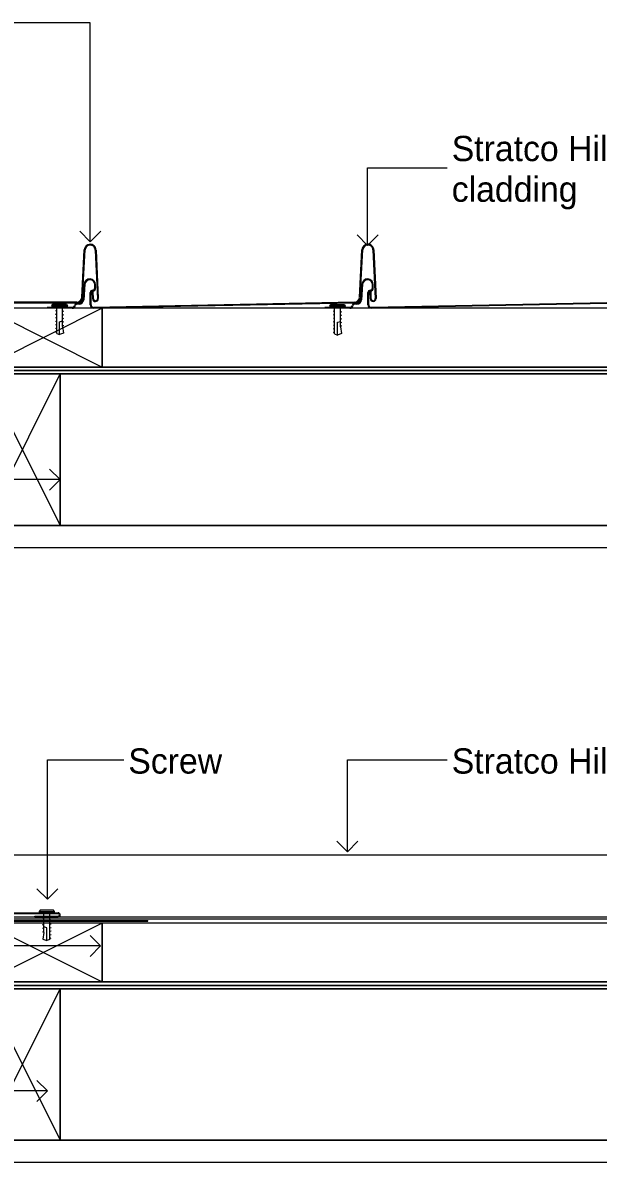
# Model space of a CAD drawing. Extents: x -2.36 to 6.66, y -3.72 to 4.13.
# Drawn here: x 4.016 to 4.358, y -3.642 to -2.966 of the extents above; entities that cross this region are included whole.
import ezdxf

# ---------------------------------------------------------------- set-up
doc = ezdxf.new("R2010")
doc.units = 0
for name, color, linetype in [('A-____-____-IDEN', 7, 'Continuous'), ('A-DETL-____-MEDM', 7, 'Continuous'), ('A-DETL-GENF-OTLN', 7, 'Continuous'), ('A-WALL-____-MCUT', 7, 'Continuous'), ('A-WALL-____-PATT', 7, 'Continuous'), ('A-WALL-FNSH-MCUT', 7, 'Continuous')]:
    doc.layers.add(name, color=color, linetype=linetype)

# ---------------------------------------------------------------- blocks, each defined once
blk = doc.blocks.new('Detail Repeating_Stratco_Hiland_Tray_Nailstrip - Rib Height 38mm_165mm Coverage-Detail Flashings - Hiland Nailstrip End Caps')
at = {"layer": 'A-DETL-____-MEDM'}
for p, q in [((0.50571, 0), (0.52057, 0)), ((0.52057, 0), (0.52057, -0.0005)), ((0.68557, 0), (0.68557, -0.0005)), ((0.338, -0.00303), (0.49297, 0)), ((0.338, -0.00353), (0.49298, -0.0005)), ((0.49148, -0.03459), (0.49017, -0.0057)), ((0.49198, -0.03457), (0.49067, -0.00568)), ((0.49301, -0.00561), (0.49313, -0.00979)), ((0.49351, -0.0056), (0.49363, -0.00977)), ((0.4945, -0.002), (0.4945, -0.00924)), ((0.495, -0.002), (0.495, -0.00924)), ((0.4995, -0.00635), (0.49802, -0.03464)), ((0.49814, -0.01418), (0.4988, -0.00504)), ((0.5, -0.00637), (0.49851, -0.03466)), ((0.49863, -0.01422), (0.49929, -0.00508)), ((0.50162, -0.00241), (0.50257, -0.00241)), ((0.50162, -0.00291), (0.50257, -0.00291)), ((0.503, -0.00303), (0.65797, 0)), ((0.503, -0.00353), (0.65798, -0.0005)), ((0.50571, -0.0005), (0.52057, -0.0005)), ((0.6595, -0.002), (0.6595, -0.00924)), ((0.66, -0.002), (0.66, -0.00924)), ((0.66314, -0.01418), (0.6638, -0.00504)), ((0.66363, -0.01422), (0.66429, -0.00508)), ((0.66662, -0.00241), (0.66757, -0.00241)), ((0.66662, -0.00291), (0.66757, -0.00291)), ((0.67071, -0.0005), (0.68557, -0.0005)), ((0.49179, -0.01206), (0.49179, -0.01397)), ((0.49229, -0.01206), (0.49229, -0.01397)), ((0.49363, -0.00977), (0.49313, -0.00979)), ((0.65679, -0.01206), (0.65679, -0.01397)), ((0.65729, -0.01206), (0.65729, -0.01397))]:
    blk.add_line(p, q, dxfattribs=at)
for centre, radius, start, end in [((0.493, -0.002), 0.002, 360, 90), ((0.50571, -0.0019), 0.0019, 90, 165.08957), ((0.658, -0.002), 0.002, 360, 90), ((0.67071, -0.0019), 0.0019, 90, 165.08957), ((0.49184, -0.00565), 0.00167, 91.69561, 181.73842), ((0.49184, -0.00565), 0.00117, 91.68553, 181.57145), ((0.49184, -0.00565), 0.00167, 1.72718, 91.74264), ((0.49184, -0.00565), 0.00117, 1.72718, 91.75272), ((0.493, -0.002), 0.0015, 0, 90), ((0.50162, -0.00525), 0.00283, 90, 175.86847), ((0.50162, -0.00525), 0.00233, 90, 175.86847), ((0.50299, -0.00653), 0.0035, 89.8838, 176.99932), ((0.50299, -0.00653), 0.003, 89.8838, 173.99932), ((0.50257, -0.00107), 0.00135, 270, 345.08957), ((0.50257, -0.00107), 0.00185, 270, 345.08957), ((0.50571, -0.0019), 0.0014, 90, 165.08957), ((0.658, -0.002), 0.0015, 0, 90), ((0.66662, -0.00525), 0.00283, 90, 175.86847), ((0.66662, -0.00525), 0.00233, 90, 175.86847), ((0.66757, -0.00107), 0.00135, 270, 345.08957), ((0.66757, -0.00107), 0.00185, 270, 345.08957), ((0.67071, -0.0019), 0.0014, 90, 165.08957), ((0.49369, -0.01206), 0.0019, 97.16746, 180), ((0.49369, -0.01206), 0.0014, 99.15451, 180), ((0.49356, -0.00924), 0.000939, 263.63492, 0), ((0.49356, -0.00924), 0.00144, 266.42376, 0), ((0.65869, -0.01206), 0.0019, 97.16746, 180), ((0.65869, -0.01206), 0.0014, 99.15451, 180), ((0.65856, -0.00924), 0.000939, 263.63492, 0), ((0.65856, -0.00924), 0.00144, 266.42376, 0), ((0.49522, -0.01397), 0.00342, 180, 355.86847), ((0.49522, -0.01397), 0.00292, 180, 355.86847), ((0.66022, -0.01397), 0.00342, 180, 355.86847), ((0.66022, -0.01397), 0.00292, 180, 355.86847), ((0.495, -0.03448), 0.00352, 181.72283, 271.72823), ((0.495, -0.03448), 0.00302, 181.65349, 271.72911), ((0.495, -0.03448), 0.00302, 271.71675, 356.99932), ((0.495, -0.03448), 0.00352, 271.71763, 356.99932)]:
    blk.add_arc(centre, radius, start, end, dxfattribs=at)
at = {"layer": 'A-DETL-GENF-OTLN'}
for p, q in [((0.51068, 0.01509), (0.513, 0.01594)), ((0.51125, 0.01102), (0.51068, 0.01509)), ((0.513, 0.01594), (0.513, 0.00832)), ((0.51475, 0.0153), (0.513, 0.01594)), ((0.51475, 0.0153), (0.51475, 0.00022)), ((0.51475, 0.0146), (0.5155, 0.01436)), ((0.5105, 0.01068), (0.51125, 0.01044)), ((0.5105, 0.00858), (0.51125, 0.00834)), ((0.51125, 0.01102), (0.51125, 0.00022)), ((0.513, 0.00832), (0.51125, 0.00782)), ((0.51475, 0.0125), (0.5155, 0.01226)), ((0.51475, 0.0104), (0.5155, 0.01016)), ((0.51475, 0.0083), (0.5155, 0.00807)), ((0.5105, 0.00648), (0.51125, 0.00624)), ((0.5105, 0.00438), (0.51125, 0.00414)), ((0.5105, 0.00228), (0.51125, 0.00205)), ((0.51475, 0.00621), (0.5155, 0.00597)), ((0.51475, 0.00411), (0.5155, 0.00387)), ((0.51475, 0.00201), (0.5155, 0.00177)), ((0.50899, -0.00222), (0.50844, -0.00128)), ((0.50845, -0.00129), (0.51755, -0.00129)), ((0.5171, -0.00058), (0.5089, -0.00058)), ((0.51701, -0.00222), (0.50899, -0.00222)), ((0.51755, -0.00129), (0.51701, -0.00222)), ((0.67399, -0.00222), (0.67344, -0.00128)), ((0.67345, -0.00129), (0.68255, -0.00129)), ((0.6821, -0.00058), (0.6739, -0.00058)), ((0.68201, -0.00222), (0.67399, -0.00222)), ((0.68255, -0.00129), (0.68201, -0.00222))]:
    blk.add_line(p, q, dxfattribs=at)
for centre, radius, start, end in [((0.51045, 0.00022), 0.0008, 270, 360), ((0.51555, 0.00022), 0.0008, 180, 270), ((0.5089, -0.00108), 0.0005, 90, 203.66982), ((0.5171, -0.00108), 0.0005, 336.33018, 90), ((0.6739, -0.00108), 0.0005, 90, 203.66982), ((0.67545, 0.00022), 0.0008, 270, 342.25596), ((0.68055, 0.00022), 0.0008, 197.74404, 270), ((0.6821, -0.00108), 0.0005, 336.33018, 90)]:
    blk.add_arc(centre, radius, start, end, dxfattribs=at)
blk = doc.blocks.new('DET_ST_Framing Detail Timber - 35x70 Batten-Detail Flashings - Hiland Nailstrip End Caps')
at = {"layer": 'A-DETL-____-MEDM'}
for p, q in [((0.07, 0.035), (0, 0.035)), ((0, 0.035), (0, 0)), ((0.07, 0), (0.07, 0.035)), ((0, 0), (0.07, 0))]:
    blk.add_line(p, q, dxfattribs=at)
at = {"layer": 'A-DETL-GENF-OTLN'}
for p, q in [((0, 0.035), (0.07, 0)), ((0.07, 0.035), (0, 0))]:
    blk.add_line(p, q, dxfattribs=at)
blk = doc.blocks.new('DET_ST_Framing Detail Timber - 45x90-Detail Flashings - Hiland Nailstrip End Caps')
at = {"layer": 'A-DETL-____-MEDM'}
for p, q in [((0.09, 0.045), (0, 0.045)), ((0, 0.045), (0, 0)), ((0.09, 0), (0.09, 0.045)), ((0, 0), (0.09, 0))]:
    blk.add_line(p, q, dxfattribs=at)
at = {"layer": 'A-DETL-GENF-OTLN'}
for p, q in [((0, 0.045), (0.09, 0)), ((0.09, 0.045), (0, 0))]:
    blk.add_line(p, q, dxfattribs=at)
blk = doc.blocks.new('DET_Screw Metal Wafer - DET_Screw Metal Wafer-Detail Flashings - Hiland Nailstrip End Caps')
at = {"layer": 'A-DETL-GENF-OTLN'}
for p, q in [((-0.00455, 0.00071), (-0.00401, 0.00164)), ((0.00455, 0.00071), (-0.00455, 0.00071)), ((-0.00401, 0.00164), (0.00401, 0.00164)), ((0.00401, 0.00164), (0.00456, 0.0007)), ((-0.0041, 0), (0.0041, 0)), ((-0.00175, -0.00259), (-0.0025, -0.00235)), ((-0.00175, -0.00468), (-0.0025, -0.00445)), ((-0.00175, -0.00678), (-0.0025, -0.00654)), ((-0.00175, -0.01588), (-0.00175, -0.0008)), ((0.00175, -0.0116), (0.00175, -0.0008)), ((0.0025, -0.00286), (0.00175, -0.00262)), ((0.0025, -0.00496), (0.00175, -0.00472)), ((-0.00175, -0.00888), (-0.0025, -0.00864)), ((-0.00175, -0.01098), (-0.0025, -0.01074)), ((-0.00175, -0.01308), (-0.0025, -0.01284)), ((0, -0.0089), (0.00175, -0.0084)), ((0, -0.01651), (0, -0.0089)), ((0.0025, -0.00706), (0.00175, -0.00682)), ((0.0025, -0.00915), (0.00175, -0.00892)), ((0.0025, -0.01125), (0.00175, -0.01102)), ((0.00175, -0.0116), (0.00232, -0.01567)), ((-0.00175, -0.01518), (-0.0025, -0.01494)), ((-0.00175, -0.01588), (0, -0.01651)), ((0.00232, -0.01567), (0, -0.01651))]:
    blk.add_line(p, q, dxfattribs=at)
for centre, radius, start, end in [((-0.0041, 0.0005), 0.0005, 156.33018, 270), ((-0.00255, -0.0008), 0.0008, 360, 90), ((0.00255, -0.0008), 0.0008, 90, 180), ((0.0041, 0.0005), 0.0005, 270, 23.66982)]:
    blk.add_arc(centre, radius, start, end, dxfattribs=at)
blk = doc.blocks.new('Detail_Stratco_Hiland_Tray_Nailstrip_Overlap End - Rib Height 25mm-Detail Flashings - Hiland Nailstrip End Caps')
at = {"layer": 'A-DETL-GENF-OTLN'}
for p, q in [((-0.04609, 0.17638), (-0.04609, 0.19038)), ((-0.04559, 0.17638), (-0.04559, 0.19038)), ((-0.04459, 0.12638), (-0.04459, 0.19038)), ((-0.04409, 0.12588), (-0.04409, 0.19038)), ((-0.04559, 0.17638), (-0.04609, 0.17638)), ((-0.11261, 0.09482), (-0.11392, 0.12371)), ((-0.11211, 0.09484), (-0.11342, 0.12373)), ((-0.11108, 0.12379), (-0.11096, 0.11962)), ((-0.11058, 0.12381), (-0.11046, 0.11963)), ((-0.10459, 0.12306), (-0.10607, 0.09477)), ((-0.10408, 0.12311), (-0.10557, 0.09474)), ((-0.10109, 0.12638), (-0.04459, 0.12638)), ((-0.10109, 0.12588), (-0.04409, 0.12588)), ((-0.11096, 0.11962), (-0.11046, 0.11963))]:
    blk.add_line(p, q, dxfattribs=at)
for centre, radius, start, end in [((-0.04509, 0.19038), 0.001, 0, 180), ((-0.04509, 0.19038), 0.0005, 0, 180), ((-0.11225, 0.12376), 0.00167, 91.69561, 181.73842), ((-0.11225, 0.12376), 0.00117, 91.68552, 181.57145), ((-0.11225, 0.12376), 0.00167, 1.72718, 91.74264), ((-0.11225, 0.12376), 0.00117, 1.72718, 91.75271), ((-0.10109, 0.12288), 0.0035, 89.8838, 176.99932), ((-0.1011, 0.12288), 0.003, 89.8838, 175.52401), ((-0.10909, 0.09493), 0.00352, 181.72283, 271.72967), ((-0.10909, 0.09493), 0.00302, 181.65349, 271.72911), ((-0.10909, 0.09493), 0.00302, 271.71675, 356.99932), ((-0.10909, 0.09493), 0.00352, 271.71907, 356.9938)]:
    blk.add_arc(centre, radius, start, end, dxfattribs=at)
blk = doc.blocks.new('Detail_Stratco_Cladding Side Profile - 38mm-Detail Flashings - Hiland Nailstrip End Caps')
at = {"layer": 'A-DETL-____-MEDM'}
for p, q in [((0.78781, 0.001), (0, 0.001)), ((0, 0), (0.78781, 0))]:
    blk.add_line(p, q, dxfattribs=at)
at = {"layer": 'A-DETL-GENF-OTLN'}
blk.add_line((0, 0.038), (0.78781, 0.038), dxfattribs=at)
blk = doc.blocks.new('DET_Screw Metal Wafer - DET_Screw Metal Wafer-V19-Detail Flashings - Hiland Nailstrip End Caps')
at = {"layer": 'A-DETL-GENF-OTLN'}
for p, q in [((-0.00175, 0.01518), (-0.0025, 0.01494)), ((-0.00175, 0.01588), (0, 0.01651)), ((-0.00175, 0.01588), (-0.00175, 0.0008)), ((0, 0.01651), (0, 0.0089)), ((0.00232, 0.01567), (0, 0.01651)), ((0.00175, 0.0116), (0.00232, 0.01567)), ((-0.00175, 0.01308), (-0.0025, 0.01284)), ((-0.00175, 0.01098), (-0.0025, 0.01074)), ((-0.00175, 0.00888), (-0.0025, 0.00864)), ((-0.00175, 0.00678), (-0.0025, 0.00654)), ((0, 0.0089), (0.00175, 0.0084)), ((0.00175, 0.0116), (0.00175, 0.0008)), ((0.0025, 0.01125), (0.00175, 0.01102)), ((0.0025, 0.00915), (0.00175, 0.00892)), ((0.0025, 0.00706), (0.00175, 0.00682)), ((-0.0041, 0), (0.0041, 0)), ((-0.00175, 0.00468), (-0.0025, 0.00445)), ((-0.00175, 0.00259), (-0.0025, 0.00235)), ((0.0025, 0.00496), (0.00175, 0.00472)), ((0.0025, 0.00286), (0.00175, 0.00262)), ((-0.00455, -0.00071), (-0.00401, -0.00164)), ((0.00455, -0.00071), (-0.00455, -0.00071)), ((-0.00401, -0.00164), (0.00401, -0.00164)), ((0.00401, -0.00164), (0.00456, -0.0007))]:
    blk.add_line(p, q, dxfattribs=at)
for centre, radius, start, end in [((-0.0041, -0.0005), 0.0005, 90, 203.66982), ((-0.00255, 0.0008), 0.0008, 270, 0), ((0.00255, 0.0008), 0.0008, 180, 270), ((0.0041, -0.0005), 0.0005, 336.33018, 90)]:
    blk.add_arc(centre, radius, start, end, dxfattribs=at)
blk = doc.blocks.new('Detail_Stratco_Hiland_Tray_End Top 1 - Rib Height 25mm-Detail Flashings - Hiland Nailstrip End Caps')
at = {"layer": 'A-DETL-GENF-OTLN'}
for p, q in [((-0.06395, -0.14495), (-0.06395, -0.04545)), ((-0.06345, -0.04545), (-0.06395, -0.04545)), ((-0.06345, -0.14545), (-0.06345, -0.04545)), ((-0.06845, -0.14295), (-0.06845, -0.0987)), ((-0.06795, -0.14345), (-0.06795, -0.0987)), ((-0.06645, -0.11245), (-0.06645, -0.0987)), ((-0.06595, -0.11245), (-0.06595, -0.0987)), ((-0.06595, -0.11245), (-0.06645, -0.11245)), ((-0.06845, -0.14295), (-0.1017, -0.14295)), ((-0.06795, -0.14345), (-0.1017, -0.14345)), ((-0.1017, -0.14495), (-0.06395, -0.14495)), ((-0.1017, -0.14545), (-0.06345, -0.14545)), ((-0.00295, -0.14545), (-0.00295, -0.14495))]:
    blk.add_line(p, q, dxfattribs=at)
for centre, radius, start, end in [((-0.0672, -0.0987), 0.00125, 0, 180), ((-0.0672, -0.0987), 0.00075, 0, 180), ((-0.1017, -0.1442), 0.00125, 90, 270), ((-0.1017, -0.1442), 0.00075, 90, 270)]:
    blk.add_arc(centre, radius, start, end, dxfattribs=at)

msp = doc.modelspace()

# ---------------------------------------------------------------- linework, layer by layer
at = {"layer": 'A-____-____-IDEN'}
for p, q in [((4.05653, -2.96559), (3.9245, -2.96559)), ((4.05653, -3.09554), (4.05653, -2.96559)), ((4.22133, -3.05169), (4.26861, -3.05169)), ((4.22133, -3.0978), (4.22133, -3.05169)), ((4.05653, -3.09554), (4.05028, -3.08929)), ((4.05653, -3.09554), (4.06278, -3.08929)), ((4.22133, -3.0978), (4.21508, -3.09155)), ((4.22133, -3.0978), (4.22758, -3.09155)), ((4.03865, -3.23679), (4.0324, -3.23054)), ((4.03865, -3.23679), (3.92653, -3.23679)), ((4.03865, -3.23679), (4.0324, -3.24304)), ((4.03115, -3.4032), (4.07647, -3.4032)), ((4.03115, -3.48591), (4.03115, -3.4032)), ((4.20938, -3.4032), (4.26861, -3.4032)), ((4.20938, -3.45771), (4.20938, -3.4032)), ((4.20938, -3.45771), (4.20313, -3.45146)), ((4.20938, -3.45771), (4.21563, -3.45146)), ((4.03115, -3.48591), (4.0249, -3.47966)), ((4.03115, -3.48591), (4.0374, -3.47966)), ((4.06274, -3.51359), (4.05649, -3.50734)), ((4.06274, -3.51359), (3.92452, -3.51359)), ((4.06274, -3.51359), (4.05649, -3.51984)), ((4.03115, -3.59966), (4.0249, -3.59341)), ((4.03115, -3.59966), (3.92653, -3.59966)), ((4.03115, -3.59966), (4.0249, -3.60591))]:
    msp.add_line(p, q, dxfattribs=at)
at = {"layer": 'A-WALL-____-MCUT'}
for p, q in [((4.68152, -3.13503), (4.06371, -3.13503)), ((4.78152, -3.17203), (3.99371, -3.17203)), ((4.68152, -3.17003), (4.06371, -3.17003)), ((4.73652, -3.17403), (4.03871, -3.17403)), ((4.73652, -3.26403), (4.03871, -3.26403)), ((4.71152, -3.5), (4.06371, -3.5)), ((4.78152, -3.537), (3.99371, -3.537)), ((4.71152, -3.535), (4.06371, -3.535)), ((4.73652, -3.539), (4.03871, -3.539)), ((4.73652, -3.629), (4.03871, -3.629))]:
    msp.add_line(p, q, dxfattribs=at)
at = {"layer": 'A-WALL-____-PATT'}
for p, q in [((4.68152, -3.13503), (4.06371, -3.13503)), ((4.06371, -3.13503), (4.06371, -3.17003)), ((4.78152, -3.17003), (3.99371, -3.17003)), ((3.99371, -3.17203), (4.75152, -3.17203)), ((4.78152, -3.17203), (3.99371, -3.17203)), ((4.06371, -3.17003), (4.68152, -3.17003)), ((3.99371, -3.17403), (4.03871, -3.17403)), ((4.03871, -3.17403), (4.73652, -3.17403)), ((4.73652, -3.17403), (4.03871, -3.17403)), ((4.03871, -3.17403), (4.03871, -3.26403)), ((4.78152, -3.26403), (3.99371, -3.26403)), ((4.03871, -3.26403), (4.73652, -3.26403)), ((3.99371, -3.27703), (4.73652, -3.27703)), ((4.71152, -3.5), (4.06371, -3.5)), ((4.06371, -3.5), (4.06371, -3.535)), ((4.78152, -3.535), (3.99371, -3.535)), ((3.99371, -3.537), (4.71152, -3.537)), ((4.78152, -3.537), (3.99371, -3.537)), ((4.06371, -3.535), (4.71152, -3.535)), ((3.99371, -3.539), (4.73652, -3.539)), ((4.73652, -3.539), (4.03871, -3.539)), ((4.03871, -3.539), (4.03871, -3.629)), ((4.78152, -3.629), (3.99371, -3.629)), ((4.03871, -3.629), (4.73652, -3.629)), ((3.99371, -3.642), (4.73652, -3.642))]:
    msp.add_line(p, q, dxfattribs=at)
at = {"layer": 'A-WALL-FNSH-MCUT'}
for p, q in [((3.99371, -3.27703), (4.78152, -3.27703)), ((3.99371, -3.642), (4.78152, -3.642))]:
    msp.add_line(p, q, dxfattribs=at)

# ---------------------------------------------------------------- block references
at = {"layer": 'A-DETL-GENF-OTLN'}
for name, p, rotation in [('Detail_Stratco_Hiland_Tray_Nailstrip_Overlap End - Rib Height 25mm-Detail Flashings - Hiland Nailstrip End Caps', (3.94743, -3.00565), 180), ('Detail Repeating_Stratco_Hiland_Tray_Nailstrip - Rib Height 38mm_165mm Coverage-Detail Flashings - Hiland Nailstrip End Caps', (4.71652, -3.13503), 180), ('DET_ST_Framing Detail Timber - 45x90-Detail Flashings - Hiland Nailstrip End Caps', (4.03871, -3.26403), 89.9999999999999), ('Detail_Stratco_Hiland_Tray_End Top 1 - Rib Height 25mm-Detail Flashings - Hiland Nailstrip End Caps', (4.13617, -3.56239), -90.00000000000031), ('DET_Screw Metal Wafer - DET_Screw Metal Wafer-V19-Detail Flashings - Hiland Nailstrip End Caps', (4.03078, -3.49394), 180), ('DET_ST_Framing Detail Timber - 45x90-Detail Flashings - Hiland Nailstrip End Caps', (4.03871, -3.629), 89.9999999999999)]:
    msp.add_blockref(name, p, dxfattribs=dict(at, rotation=rotation))
for name, p in [('DET_ST_Framing Detail Timber - 35x70 Batten-Detail Flashings - Hiland Nailstrip End Caps', (3.99371, -3.17003)), ('DET_Screw Metal Wafer - DET_Screw Metal Wafer-Detail Flashings - Hiland Nailstrip End Caps', (4.03838, -3.13421)), ('Detail_Stratco_Cladding Side Profile - 38mm-Detail Flashings - Hiland Nailstrip End Caps', (3.99371, -3.4975)), ('DET_ST_Framing Detail Timber - 35x70 Batten-Detail Flashings - Hiland Nailstrip End Caps', (3.99371, -3.535))]:
    msp.add_blockref(name, p, dxfattribs=at)

# ---------------------------------------------------------------- texts
at = {"layer": 'A-____-____-IDEN'}
for s, p in [('Stratco Hiland Tray Nailstrip', (4.27133, -3.04772)), ('cladding', (4.27133, -3.07186)), ('Stratco Hiland Tray cladding', (4.27133, -3.4113)), ('Screw', (4.07918, -3.4113))]:
    msp.add_text(s, height=0.015, dxfattribs=at).set_placement(p)

doc.saveas('drawing.dxf')
